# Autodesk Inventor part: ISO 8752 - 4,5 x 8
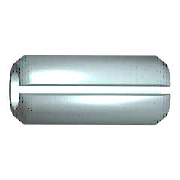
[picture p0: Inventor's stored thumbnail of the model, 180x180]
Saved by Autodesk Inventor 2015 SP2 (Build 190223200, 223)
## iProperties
Created: 2012-02
Part Number: ISO 8752 - 4,5 x 8
Material: Edelstahl, austenitisch
Description: Spannstift
Document SubType Name: Modeling
Standard: ISO 8752
Designer: rYan
Standards Organization: DIN
Language: de-DE
Size Designation: 4,5 x 8
Categories: <MemberInstance><Categories><Category DisplayName="Verbindungselemente" InternalName="e4da775c-781d-43d5-af7c-5136215cf5a6" Mnemonic="FSTN"><Category DisplayNam
Density: 8.03 g/cm^3
Mass: 0.77376 g
Surface Area: 2.31713 cm^2
Volume: 0.0963587 cm^3
Appearance: Halbpoliert
IsCustomPart: 0
Author: rYan
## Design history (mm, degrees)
sketch "Skizze1"
  geometry: L1 (0, 1.55)-(0, 2.336); L2 (0, 2.336)-(0.8, 2.55); L3 (0.8, 2.55)-(7.2, 2.55); L4 (7.2, 2.55)-(8, 2.336); L5 (8, 2.336)-(8, 1.55); L6 (8, 0)-(0, 0); L7 (0, 1.55)-(8, 1.55); L8 (0, 1.55)-(0, 0); L9 (8, 1.55)-(8, 0); L10 (0, 3.06)-(0, -0.51) reference; L11 (-1.6, 0)-(9.6, 0) reference
  constraints: 18 end point, 3 parallel, 3 perpendicular, 1 coincident, 1 point on line, 1 vertical
  dimensions: "d0" = 8 distance between parallel lines of L5 L1 (= NLG); "d1" = 5.1 diameter of L3 L6 (= NND1); "d2" = 3.1 diameter of L7 L6 (= NND1 - 2 x SD); "d3" = 15 deg angle of L3 L2 (= FAWI); "d4" = 15 deg angle of L4 L3 (= FAWI); "d7" = 0.21436 vertical distance of L2.end L1.end (computed from SD, FAWI, PHH); "d8" = 0.21436 vertical distance of L3.end L4.end (computed from SD, FAWI, PHH1)
revolve "Körper" sketch "Skizze1" stored, may be unused: angle "d10" = 90 deg
workplane "Work Plane1"
sketch "Skizze2"
  geometry: L1 (-0.194, 1.538)-(-0.32, 2.53); L2 (0.194, 1.538)-(0.32, 2.53); L3 (0, 3.06)-(0, -0.51) reference; L4 (-0.447, 0)-(0.447, 0) reference; A1 r 2.55 centre (0, 0) between (0.32, 2.53) and (-0.32, 2.53); A2 r 1.55 centre (0, 0) between (0.194, 1.538) and (-0.194, 1.538); 1 further point
  constraints: 4 end point, 4 point on circle, 2 centre point, 2 coincident, 2 horizontal alignment, 1 other
  dimensions: "d11" = 2.55 radius of A1 (= 0.5 x NND1); "d12" = 1.55 radius of A2 (= -SD + 0.5 x NND1); "d14" = 1 distance of L1.start L1.end (= SD); "d15" = 7.2 deg angle of L3 L1
extrude "Schnitt" cut sketch "Skizze2" stored distance "d5" = 8 (= NLG); taper "d6" = 0 deg
body "Solid1"
other parameters: "NND" = 4.5 [user parameter], "NLG" = 8 [user parameter; used in 3 equation terms], "SD" = 1 [user parameter; used in 5 equation terms], "PHH" = 0.8 [user parameter; used in 2 equation terms], "PHH1" = 0.8 (= PHH) [user parameter; used in 1 equation term], "FAWI" = 15 deg [user parameter; used in 4 equation terms], "d9" = 4 (= 0.5 x NLG), "d31" = 0, "d32" = 0, "d33" = 0, "NND1" = 5.1 [user parameter; used in 4 equation terms]
